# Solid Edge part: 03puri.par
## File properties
Username: User
Author: User
Template: Iso Metric Part.par
Last saved by: User
Revision: 6
Application: Solid Edge
Accuracy: 0,990
Face Style: Model Default
Fill Style: Normal
Coef. of Thermal Exp: 0.0
Thermal Conductivity: 0.0
Specific Heat: 0.0
Modulus of Elasticity: 0.0
Poisson's Ratio: 0.0
Yield Stress: 0.0
Ultimate Stress: 0.0
Elongation: 0.0
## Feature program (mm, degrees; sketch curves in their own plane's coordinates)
thicken "unnamed Thicken 1"
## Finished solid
Body 1: solid body, 5 faces, 9 edges, 6 vertices.
  Faces by surface: spline 4, offset 1
  Edges by curve: curve on surface 9
Body 2: sheet body, 1 face, 3 edges, 3 vertices.
  Faces by surface: spline 1
  Edges by curve: curve on surface 3
Bounding box of the edges (mm; curved faces can reach further): 129.344 x 45.524 x 220.000, from (8.4165, -0.5, 72.5713) to (137.7603, 45.0243, 292.5715).
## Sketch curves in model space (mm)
spline (0, 0, 72.5715) -> (0, 38.1946, 185.3575) -> (0, 0, 292.5715)
spline (8.4165, 0, 292.5715) -> (72.0581, 0, 178.1941) -> (137.7603, 0, 72.5715)
line (8.4165, 0, 72.5715) -> (8.4165, 0, 292.5715)
line (8.4165, 0, 72.5715) -> (137.7603, 0, 72.5715)
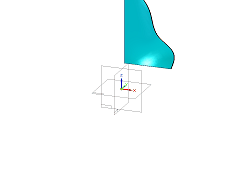
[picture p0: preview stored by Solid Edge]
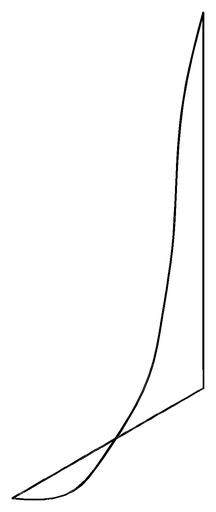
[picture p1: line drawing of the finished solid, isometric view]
